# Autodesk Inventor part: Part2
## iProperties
Shininess: 77.0
Angle Display Precision: 2
Document Length Units: 11269
Document Angle Units: 11279
Document Time Units: 11290
Document Mass Units: 11283
Document Length Units Precision: 3
Document Angle Units Precision: 2
Created: 2001-12
Part Number: Part2
Document SubType Name: Modeling
Designer: Renu Muthoo
Density: 0.0
Volumn: 0.0
Area: 0.0
PropertySet Name: Model Information
Control State: 0
Master: False
Checked Out: False
Author: Renu Muthoo
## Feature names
1. Extrusion1
2. Extrusion2
3. Extrusion3
4. Mirror1
5. Fillet1
6. Hole1
